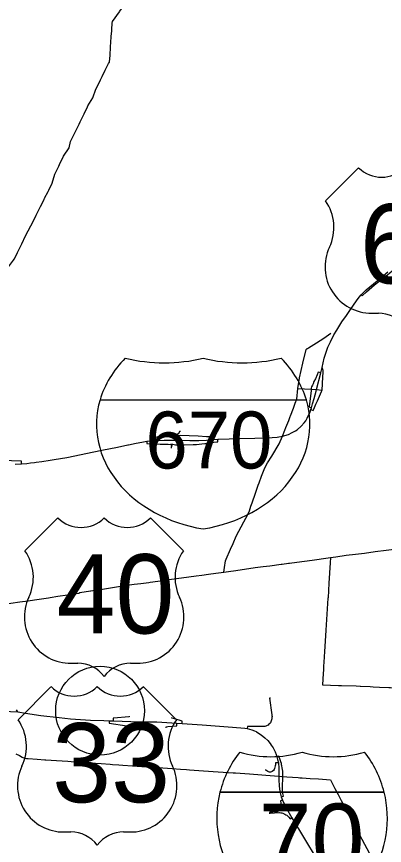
# Model space of a CAD drawing. Extents: x -7.1 to 34, y 0 to 22.
# Drawn here: x 5.986 to 6.584, y 16.769 to 18.117 of the extents above; entities that cross this region are included whole.
import ezdxf

# ---------------------------------------------------------------- set-up
doc = ezdxf.new("R2010")
doc.units = 0
for name, color, linetype in [('GM_X_Interchange_Ramps', 7, 'Continuous'), ('GM_X_Interstate_Route', 7, 'Continuous'), ('GM_X_Interstate_Shield', 7, 'Continuous'), ('GM_X_State_Route', 7, 'Continuous'), ('GM_X_US_Route', 7, 'Continuous'), ('GM_X_US_Shield', 7, 'Continuous'), ('SH_Text', 7, 'Continuous')]:
    doc.layers.add(name, color=color, linetype=linetype)

msp = doc.modelspace()

# ---------------------------------------------------------------- linework, layer by layer
at = {"layer": 'GM_X_Interchange_Ramps'}
for points in [[(6.5463, 17.6647), (6.5481, 17.6631), (6.5551, 17.6695), (6.5681, 17.6805), (6.5893, 17.6972), (6.6006, 17.7068), (6.6074, 17.7125), (6.6125, 17.7162), (6.6167, 17.7191), (6.6281, 17.7259), (6.6674, 17.748), (6.6719, 17.7503), (6.6762, 17.7523), (6.6759, 17.7539)], [(6.4805, 17.5377), (6.4763, 17.5386), (6.4747, 17.5347), (6.4718, 17.5282), (6.4695, 17.5234), (6.4679, 17.5201), (6.4668, 17.5174), (6.4657, 17.515), (6.4651, 17.5129), (6.4651, 17.511)], [(6.4651, 17.511), (6.465, 17.5086), (6.4623, 17.4874), (6.4617, 17.4822), (6.4655, 17.4806)], [(6.4644, 17.478), (6.468, 17.4765), (6.469, 17.4787), (6.4727, 17.4869), (6.4752, 17.4922), (6.4818, 17.5071), (6.4827, 17.5096)], [(6.2521, 17.4424), (6.2509, 17.4426), (6.25, 17.4407), (6.2487, 17.4387), (6.2475, 17.4378), (6.246, 17.437), (6.2451, 17.4367), (6.2365, 17.4364), (6.2316, 17.4361), (6.228, 17.4359), (6.2238, 17.4353), (6.2188, 17.4345), (6.2137, 17.4333), (6.2049, 17.4315), (6.2039, 17.4313), (6.2042, 17.4273)], [(6.2501, 17.4355), (6.2481, 17.4356), (6.2449, 17.4356), (6.2451, 17.4367)], [(6.3051, 17.4294), (6.305, 17.4335), (6.2945, 17.4338), (6.2809, 17.4346), (6.2666, 17.4351), (6.2526, 17.4357), (6.2501, 17.4355)], [(6.1975, 17.4267), (6.1978, 17.4227), (6.2079, 17.4222), (6.2195, 17.422), (6.2321, 17.4215), (6.2361, 17.4213), (6.2372, 17.4211), (6.2375, 17.4208), (6.2378, 17.4204), (6.2379, 17.4199), (6.238, 17.4195), (6.238, 17.419), (6.2379, 17.4186), (6.2378, 17.4181), (6.2375, 17.4177), (6.2365, 17.4164), (6.2377, 17.4156)], [(6.2361, 17.4213), (6.236, 17.422), (6.24, 17.4216), (6.2422, 17.4211)], [(6.2422, 17.4211), (6.2441, 17.4209), (6.2474, 17.4208), (6.2583, 17.4204), (6.2729, 17.4212), (6.2782, 17.4213), (6.2828, 17.4217), (6.2872, 17.4221), (6.2917, 17.4227), (6.2958, 17.4231), (6.3025, 17.4242), (6.3114, 17.4254), (6.313, 17.4257), (6.313, 17.4284), (6.313, 17.4299)], [(5.9935, 17.3897), (5.9935, 17.3943), (5.9612, 17.3954)], [(6.3985, 17.0091), (6.3969, 17.0086), (6.401, 16.982), (6.4011, 16.9807), (6.4012, 16.9792), (6.4011, 16.9773), (6.401, 16.9754), (6.4006, 16.9736), (6.4001, 16.9719), (6.3993, 16.9702), (6.3985, 16.969), (6.3974, 16.9676), (6.3963, 16.9664), (6.3948, 16.9652), (6.3933, 16.9643), (6.3914, 16.9634), (6.3897, 16.9629), (6.3882, 16.9626), (6.3686, 16.9626), (6.3611, 16.9626), (6.3606, 16.9595)], [(5.9876, 16.9866), (5.9857, 16.9897)], [(6.1686, 16.9798), (6.1686, 16.9786), (6.1435, 16.9764), (6.143, 16.9764), (6.1428, 16.972)], [(6.2548, 16.9677), (6.255, 16.9717), (6.2502, 16.973), (6.2425, 16.9751), (6.2384, 16.9763), (6.2385, 16.9773)], [(6.1362, 16.9722), (6.1361, 16.9684), (6.1651, 16.964), (6.1674, 16.9636), (6.1673, 16.9626)], [(6.2291, 16.9604), (6.2292, 16.962), (6.232, 16.9626), (6.2386, 16.9633), (6.2462, 16.964), (6.2464, 16.9681)], [(6.4189, 16.8814), (6.4188, 16.8843), (6.4188, 16.8872), (6.4186, 16.89), (6.4183, 16.8928), (6.4179, 16.8957), (6.4173, 16.8986), (6.4169, 16.9007), (6.4164, 16.9028), (6.4156, 16.9056), (6.4146, 16.9088), (6.4125, 16.9143), (6.4093, 16.9135)], [(6.4115, 16.9039), (6.4071, 16.9035), (6.4068, 16.9004), (6.4065, 16.8987), (6.4059, 16.8965), (6.4054, 16.8947), (6.4046, 16.8928), (6.4034, 16.891), (6.4015, 16.8895), (6.4002, 16.8889), (6.3987, 16.8886), (6.3971, 16.8886), (6.3953, 16.889), (6.3943, 16.8894), (6.3909, 16.8917), (6.3902, 16.8917)], [(6.4162, 16.8482), (6.4197, 16.8495), (6.4189, 16.854), (6.4186, 16.8563), (6.4183, 16.8584), (6.4182, 16.8606), (6.4181, 16.8628), (6.4181, 16.8647), (6.4182, 16.8666), (6.4187, 16.8782), (6.4188, 16.8797), (6.4188, 16.8805), (6.4189, 16.8814)], [(6.4184, 16.8432), (6.4148, 16.842), (6.416, 16.8349), (6.4161, 16.8334), (6.4159, 16.8316), (6.4155, 16.8301), (6.415, 16.829), (6.4141, 16.8276), (6.413, 16.8264), (6.4118, 16.8255), (6.4105, 16.8247), (6.4095, 16.8243), (6.4084, 16.8239), (6.407, 16.8237), (6.4058, 16.8237), (6.4049, 16.8238), (6.4034, 16.8241), (6.4027, 16.8243), (6.4021, 16.8245), (6.4006, 16.8254), (6.3997, 16.8261), (6.3974, 16.8282), (6.3958, 16.828)], [(6.4027, 16.8243), (6.4024, 16.8235), (6.398, 16.8233), (6.3964, 16.8231)], [(6.3965, 16.8219), (6.3984, 16.8221), (6.4121, 16.8229), (6.4136, 16.8229), (6.4154, 16.8227), (6.4171, 16.8223), (6.4186, 16.8219), (6.4201, 16.8214), (6.422, 16.8205), (6.4238, 16.8194), (6.4252, 16.8184), (6.4269, 16.817), (6.4283, 16.8155), (6.4306, 16.8128), (6.4333, 16.8144)]]:
    msp.add_lwpolyline(points, dxfattribs=at)
at = {"layer": 'GM_X_Interstate_Route'}
for points in [[(6.5247, 17.6342), (6.5289, 17.6404), (6.5384, 17.6546), (6.5428, 17.6607), (6.5463, 17.6647), (6.5498, 17.6685), (6.5542, 17.6726), (6.5601, 17.6777), (6.572, 17.6875), (6.5895, 17.7019)], [(6.4827, 17.5463), (6.4844, 17.5541), (6.4863, 17.5614), (6.4893, 17.5712), (6.4921, 17.5792), (6.4962, 17.5882), (6.5019, 17.5996), (6.5065, 17.6073), (6.5149, 17.6206), (6.5225, 17.631), (6.5247, 17.6342)], [(6.4729, 17.5078), (6.4736, 17.5105), (6.4805, 17.5377), (6.4827, 17.5463)], [(6.4184, 17.4346), (6.428, 17.4376), (6.4342, 17.4405), (6.4392, 17.4432), (6.4421, 17.4452), (6.4487, 17.4508), (6.4537, 17.4562), (6.4563, 17.4599), (6.4585, 17.4639), (6.4631, 17.4741), (6.4644, 17.478), (6.4655, 17.4806), (6.4673, 17.4871), (6.4697, 17.4958), (6.4729, 17.5078)], [(6.1668, 17.4206), (6.1679, 17.4208), (6.1805, 17.4236), (6.1892, 17.4251), (6.1975, 17.4267), (6.2042, 17.4273), (6.2139, 17.4279), (6.2259, 17.4284), (6.2399, 17.4285), (6.2467, 17.4283), (6.2674, 17.4277), (6.2823, 17.4278), (6.2946, 17.4285), (6.3051, 17.4294), (6.313, 17.4299), (6.3139, 17.43), (6.3488, 17.4309), (6.3734, 17.4316), (6.3904, 17.4322), (6.4014, 17.4327), (6.4097, 17.4334), (6.4184, 17.4346)], [(6.0403, 17.3957), (6.047, 17.3966), (6.0674, 17.4002), (6.0806, 17.4028), (6.0981, 17.4067), (6.1245, 17.4118), (6.1499, 17.417), (6.1668, 17.4206)], [(6.0146, 17.3921), (6.0174, 17.3924), (6.0268, 17.3938), (6.0403, 17.3957)], [(5.9834, 17.3891), (5.9935, 17.3897), (6.0025, 17.3905), (6.0085, 17.3913), (6.0146, 17.3921)], [(5.951, 16.9883), (5.9542, 16.9881), (5.9757, 16.987), (5.9876, 16.9866), (6.0001, 16.9845), (6.0249, 16.9809), (6.0549, 16.9776), (6.0732, 16.9751), (6.1058, 16.9733), (6.1277, 16.9725), (6.1362, 16.9722), (6.1428, 16.972), (6.1864, 16.9706), (6.2141, 16.9702), (6.2464, 16.9681), (6.2548, 16.9677), (6.2876, 16.9656), (6.3368, 16.9618), (6.357, 16.9601), (6.3606, 16.9595), (6.3683, 16.9573), (6.3727, 16.9556), (6.3752, 16.9544)], [(6.3752, 16.9544), (6.3759, 16.9541), (6.3836, 16.9493), (6.3894, 16.9443), (6.3942, 16.94), (6.3983, 16.9352), (6.4, 16.9327), (6.4029, 16.9282), (6.4047, 16.9246)], [(6.4047, 16.9246), (6.4063, 16.9218), (6.4082, 16.9173), (6.4093, 16.9135), (6.4102, 16.9093), (6.4115, 16.9039), (6.4121, 16.8949), (6.4124, 16.8819)], [(6.4124, 16.8819), (6.4125, 16.876), (6.4126, 16.8661), (6.414, 16.8573), (6.4162, 16.8482), (6.4184, 16.8432), (6.4196, 16.8403), (6.4214, 16.8365), (6.4243, 16.8304), (6.4333, 16.8144), (6.4935, 16.7147), (6.5223, 16.6633), (6.5434, 16.6322), (6.5549, 16.6221), (6.5591, 16.6194), (6.5633, 16.6172)]]:
    msp.add_lwpolyline(points, dxfattribs=at)
at = {"layer": 'GM_X_Interstate_Shield'}
for p, q in [((6.4571, 17.4935), (6.1215, 17.4935)), ((6.4571, 17.4935), (6.1215, 17.4935)), ((6.3166, 16.8561), (6.5836, 16.8561)), ((6.5836, 16.8561), (6.3166, 16.8561)), ((6.5836, 16.8561), (6.3166, 16.8561))]:
    msp.add_line(p, q, dxfattribs=at)
for centre, start, end in [((6.4848, 16.8136), 141.669, 165.8066), ((6.3994, 17.0872), 253.0091, 286.9909), ((6.5008, 17.0872), 253.0091, 286.9909), ((6.4154, 16.8136), 14.1934, 38.331), ((6.4848, 16.8136), 165.8066, 258.463), ((6.4154, 16.8136), 281.537, 14.1934)]:
    msp.add_arc(centre, 0.1735, start, end, dxfattribs=at)
for centre, start_param, end_param in [((6.3326, 17.4539), 2.47259, 2.911027), ((6.2259, 17.7275), 4.415841, 5.008937), ((6.3526, 17.7275), 4.415841, 5.008937), ((6.2459, 17.4539), 0.230566, 0.669003), ((6.3326, 17.4539), 2.911027, 4.511031), ((6.2459, 17.4539), 4.913747, 6.513751)]:
    msp.add_ellipse(centre, major_axis=(0.2169, 0), ratio=0.8, start_param=start_param, end_param=end_param, dxfattribs=at)
at = {"layer": 'GM_X_State_Route'}
for points in [[(6.1408, 18.099), (6.1408, 18.0993), (6.1411, 18.1029), (6.1413, 18.1064), (6.1415, 18.1089), (6.1532, 18.1248), (6.1537, 18.1256), (6.1612, 18.1362), (6.1701, 18.1514), (6.179, 18.1661), (6.1844, 18.175)], [(6.1243, 18.0185), (6.1248, 18.0195), (6.1298, 18.0299), (6.135, 18.0406), (6.1371, 18.0427), (6.1377, 18.0539), (6.1384, 18.067), (6.1385, 18.0681), (6.139, 18.0747), (6.1397, 18.0845), (6.1404, 18.0934), (6.1408, 18.0988), (6.1408, 18.099)], [(6.0003, 17.7603), (6.0089, 17.7766), (6.0168, 17.7924), (6.0175, 17.7941), (6.0246, 17.808), (6.0306, 17.8193), (6.0313, 17.8214), (6.037, 17.8325), (6.038, 17.8348), (6.0436, 17.8463), (6.0479, 17.8608), (6.0544, 17.8739), (6.0555, 17.8762), (6.062, 17.8899), (6.071, 17.9036), (6.0734, 17.9138), (6.0754, 17.9179), (6.0805, 17.9281), (6.0819, 17.9311), (6.0874, 17.9421), (6.0892, 17.9457), (6.0957, 17.9589), (6.101, 17.9699), (6.1018, 17.9717), (6.1096, 17.9845), (6.1149, 17.999), (6.1173, 18.0039), (6.1221, 18.0139), (6.1238, 18.0175), (6.1243, 18.0185)], [(5.8895, 17.6087), (5.8913, 17.6109), (5.9093, 17.6345), (5.9168, 17.6423), (5.9224, 17.6491), (5.9406, 17.672), (5.9462, 17.6781), (5.9532, 17.6871), (5.9667, 17.7036), (5.9724, 17.7099), (5.9793, 17.7189), (5.9808, 17.721), (5.9818, 17.7227), (5.9859, 17.7307), (5.9872, 17.7335), (5.9932, 17.7455), (5.994, 17.7476), (6.0003, 17.7603)], [(6.4964, 17.2373), (6.5049, 17.2386), (6.5219, 17.2413), (6.5371, 17.2431), (6.5519, 17.2447), (6.5689, 17.247), (6.5869, 17.2493), (6.6044, 17.2516), (6.6214, 17.2541), (6.6373, 17.2564), (6.645, 17.2575), (6.6591, 17.2593), (6.663, 17.2599), (6.6784, 17.2614), (6.679, 17.2615)]]:
    msp.add_lwpolyline(points, dxfattribs=at)
at = {"layer": 'GM_X_US_Route'}
for points in [[(6.4586, 17.577), (6.4591, 17.5773), (6.4606, 17.5782), (6.4737, 17.5864), (6.4855, 17.5939), (6.4969, 17.6021)], [(6.3229, 17.2138), (6.3241, 17.2211), (6.3256, 17.2321), (6.3266, 17.235), (6.3335, 17.2513), (6.338, 17.2603), (6.3428, 17.2721), (6.3554, 17.2955), (6.3617, 17.3076), (6.3645, 17.3132), (6.367, 17.321), (6.3687, 17.3262), (6.3743, 17.342), (6.3789, 17.3551), (6.3803, 17.3591), (6.384, 17.37), (6.3897, 17.3831), (6.3941, 17.3914), (6.4009, 17.4022), (6.4126, 17.4223), (6.4184, 17.4346), (6.4222, 17.4443), (6.4239, 17.4487), (6.4284, 17.4603), (6.4309, 17.4668), (6.4312, 17.4676), (6.4359, 17.4801), (6.4391, 17.4886), (6.4414, 17.4948), (6.4433, 17.5121), (6.4458, 17.529), (6.4459, 17.5294), (6.4513, 17.5536), (6.4566, 17.5759), (6.4586, 17.577)], [(6.4827, 17.5096), (6.484, 17.5309), (6.4845, 17.5388), (6.4845, 17.5413), (6.4827, 17.5463)], [(6.4433, 17.5121), (6.4651, 17.511), (6.4736, 17.5105), (6.4827, 17.5096)], [(6.4294, 17.2283), (6.4416, 17.2299), (6.4664, 17.2332), (6.4666, 17.2332), (6.4703, 17.2337), (6.489, 17.2363), (6.4964, 17.2373)], [(6.4964, 17.2373), (6.4958, 17.2288), (6.4938, 17.196)], [(6.3423, 17.2166), (6.3738, 17.2211), (6.3868, 17.2228), (6.3975, 17.2242), (6.4162, 17.2267), (6.4175, 17.2268), (6.4281, 17.2281), (6.4287, 17.2282), (6.4293, 17.2283), (6.4294, 17.2283)], [(6.2341, 17.2017), (6.2777, 17.2076), (6.2868, 17.2089), (6.2978, 17.2105), (6.3098, 17.2122), (6.3229, 17.2138)], [(6.3229, 17.2138), (6.3302, 17.2148)], [(6.3302, 17.2148), (6.3302, 17.2148), (6.3423, 17.2166)], [(5.9436, 17.1585), (5.953, 17.1601), (5.9547, 17.1604), (5.9563, 17.1606), (5.9718, 17.1625), (5.9761, 17.1631), (5.9908, 17.1653), (6.0045, 17.1673), (6.015, 17.1688), (6.0224, 17.1699), (6.0375, 17.1722), (6.0402, 17.1726), (6.0526, 17.1745), (6.0685, 17.1768), (6.0869, 17.1796), (6.0884, 17.1807), (6.1059, 17.1833), (6.1063, 17.1834), (6.1189, 17.1853), (6.122, 17.1857), (6.1416, 17.1887), (6.158, 17.1912), (6.1769, 17.1941)], [(6.1769, 17.1941), (6.1878, 17.1955), (6.2007, 17.1971), (6.203, 17.1974), (6.2316, 17.2014), (6.2341, 17.2017), (6.2341, 17.2017)], [(6.4938, 17.196), (6.4938, 17.1959), (6.4923, 17.1719), (6.4922, 17.1712), (6.4906, 17.1456), (6.489, 17.1196), (6.489, 17.119), (6.4875, 17.1022), (6.4875, 17.1014), (6.4865, 17.0847), (6.4854, 17.0674), (6.4854, 17.067), (6.4851, 17.0616), (6.4847, 17.0549)], [(6.4847, 17.0549), (6.4843, 17.0488), (6.4832, 17.0306)], [(6.4832, 17.0306), (6.5095, 17.0297), (6.5145, 17.0295), (6.538, 17.0291), (6.5444, 17.0284), (6.5449, 17.0284), (6.5607, 17.0277), (6.5655, 17.0275), (6.5758, 17.027), (6.5915, 17.0264), (6.5938, 17.0263), (6.6077, 17.0257), (6.6079, 17.0257), (6.6229, 17.0252), (6.638, 17.0247), (6.6532, 17.0242), (6.6608, 17.024)], [(5.9844, 16.9185), (5.9903, 16.9155), (5.9946, 16.9132), (5.9987, 16.9113), (6.0017, 16.9107), (6.0044, 16.9105), (6.0194, 16.9095), (6.0319, 16.9087), (6.0335, 16.9086), (6.0508, 16.9073), (6.0689, 16.9062), (6.0856, 16.905), (6.0948, 16.9044), (6.1052, 16.9037), (6.1233, 16.9025), (6.1382, 16.9014), (6.1417, 16.9012), (6.1518, 16.9005), (6.1586, 16.9), (6.1742, 16.8991), (6.1819, 16.8985), (6.1897, 16.898), (6.2093, 16.8965), (6.2238, 16.8955), (6.2389, 16.8944), (6.2525, 16.8935), (6.2623, 16.8928), (6.2672, 16.8924), (6.2822, 16.8915), (6.3053, 16.8898), (6.338, 16.8876), (6.3419, 16.8873), (6.3644, 16.8856), (6.3844, 16.8841)], [(6.3844, 16.8841), (6.3911, 16.8836), (6.4124, 16.8819), (6.4173, 16.8815)], [(6.4173, 16.8815), (6.4189, 16.8814), (6.4255, 16.881), (6.444, 16.8797), (6.4464, 16.8795)], [(6.4464, 16.8795), (6.4505, 16.8793), (6.4631, 16.8784), (6.4769, 16.8775), (6.4963, 16.8762)], [(6.4963, 16.8762), (6.4969, 16.8749), (6.5035, 16.8621), (6.5088, 16.8523), (6.5139, 16.8427), (6.5211, 16.829), (6.5307, 16.8108), (6.5354, 16.8019), (6.5552, 16.7642), (6.5672, 16.7413), (6.5707, 16.7346), (6.5737, 16.7287), (6.5752, 16.7257)]]:
    msp.add_lwpolyline(points, dxfattribs=at)
at = {"layer": 'GM_X_US_Shield'}
for p, q in [((6.542, 17.871), (6.4883, 17.8173)), ((6.5634, 17.6348), (6.5742, 17.6348)), ((6.053, 17.3019), (5.9993, 17.2482)), ((6.257, 17.2482), (6.2033, 17.3019)), ((6.0745, 17.0657), (6.0852, 17.0657)), ((6.1711, 17.0657), (6.1819, 17.0657)), ((6.0417, 17.0275), (5.9881, 16.9738)), ((6.2458, 16.9738), (6.1921, 17.0275)), ((6.0632, 16.7913), (6.074, 16.7913)), ((6.1599, 16.7913), (6.1706, 16.7913))]:
    msp.add_line(p, q, dxfattribs=at)
for centre, radius, start, end in [((6.5795, 17.9094), 0.0537, 225.573, 314.427), ((6.4267, 17.7742), 0.0752, 334.5471, 35.0009), ((6.5626, 17.71), 0.0752, 154.8319, 270.6383), ((6.5742, 17.5811), 0.0537, 36.8699, 90), ((6.0906, 17.3402), 0.0537, 225.573, 314.427), ((6.1658, 17.3402), 0.0537, 225.573, 314.427), ((5.9378, 17.2051), 0.0752, 334.5471, 35.0009), ((6.3186, 17.2051), 0.0752, 144.9991, 205.4529), ((6.0737, 17.1408), 0.0752, 154.8319, 270.6383), ((6.1827, 17.1408), 0.0752, 269.3617, 25.1681), ((6.0852, 17.012), 0.0537, 36.8699, 90), ((6.1711, 17.012), 0.0537, 90, 143.1301), ((6.0793, 17.0659), 0.0537, 225.573, 314.427), ((6.1545, 17.0659), 0.0537, 225.573, 314.427), ((5.9265, 16.9307), 0.0752, 334.5471, 35.0009), ((6.3073, 16.9307), 0.0752, 144.9991, 205.4529), ((6.0624, 16.8665), 0.0752, 154.8319, 270.6383), ((6.1714, 16.8665), 0.0752, 269.3617, 25.1681), ((6.074, 16.7376), 0.0537, 36.8699, 90), ((6.1599, 16.7376), 0.0537, 90, 143.1301)]:
    msp.add_arc(centre, radius, start, end, dxfattribs=at)
at = {"layer": 'SH_Text'}
msp.add_circle((6.1215, 16.9885), 0.0722, dxfattribs=at)

# ---------------------------------------------------------------- texts
at = {"layer": 'GM_X_Interstate_Shield'}
for s, height, p in [('670', 0.09255, (6.1952, 17.3822)), ('70', 0.11569, (6.3795, 16.7217))]:
    msp.add_text(s, height=height, dxfattribs=at).set_placement(p)
at = {"layer": 'GM_X_US_Shield'}
for s, p in [('62', (6.5442, 17.6831)), ('40', (6.0508, 17.114)), ('33', (6.0436, 16.8396))]:
    msp.add_text(s, height=0.12885, dxfattribs=at).set_placement(p)

doc.saveas('drawing.dxf')
